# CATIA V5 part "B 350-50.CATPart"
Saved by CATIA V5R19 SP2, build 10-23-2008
Part number: B 350-50
Bounding box of the stored display mesh (mm): x -15.868 to 15.868, y -15.868 to 15.868, z 0 to 150
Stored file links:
  C:\Users\Bora\Desktop\3D Katı model\B serisi\B 350\B 350-50.CATPart
  C:\Program Files\Dassault Systemes\B19\intel_a\reffiles\standard\MetricThickPitch.txt
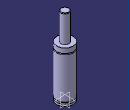
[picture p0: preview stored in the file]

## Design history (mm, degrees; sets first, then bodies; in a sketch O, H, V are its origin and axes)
Body1 (main body)
  Sketch1 on yz-plane, origin (0, 0, 0), H (0, 1, 0), V (0, 0, 1)
    point P1 (16, 88.5)
    point P4 (16, 86.5)
    point P7 (16, 88.5)
    point P8 (16, 86.5)
    point P9 (8, 149)
    point P11 (8, 149)
    line L1 (16, 88.5) -> (16, 98)
    line L2 (16, 7.5) -> (16, 86.5)
    line L3 (13.5, 7.5) -> (13.5, 4)
    arc A1 centre (16, 87.5) radius 1 from (16, 88.5) to (16, 86.5) ccw
    arc A2 centre (7, 149) radius 1 from (8, 149) to (7, 150) ccw
    line L4 (8, 149) -> (8, 98)
    line L5 (16, 0) -> (16, 4)
    line L6 (7, 150) -> (0, 150)
    point P15 (0, 150)
    line L7 (8, 98) -> (16, 98)
    line L8 (0, 0) -> (16, 0)
    line L9 (13.5, 7.5) -> (16, 7.5)
    line L10 (13.5, 4) -> (16, 4)
    coincidence: P15 V, P1 P7, P4 P8, P9 P11
    tangency: L6 A2
    horizontal: L7 H, L8 H, L9 H, L10 H
  Shaft1: profile Sketch1, axis Sketch1.V, angle 360
  Sketch2 on face of Shaft1 from Sketch1.L8, origin (0, 0, 0), H (1, 0, 0), V (0, -1, 0)
    point P1 (0, 0)
  Hole1: placed by Sketch2, at (0, 0, 0) direction (0, 0, 1), diameter 6.647, depth 7, threaded "M8", thread diameter 8, thread depth 7, pitch 1.25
